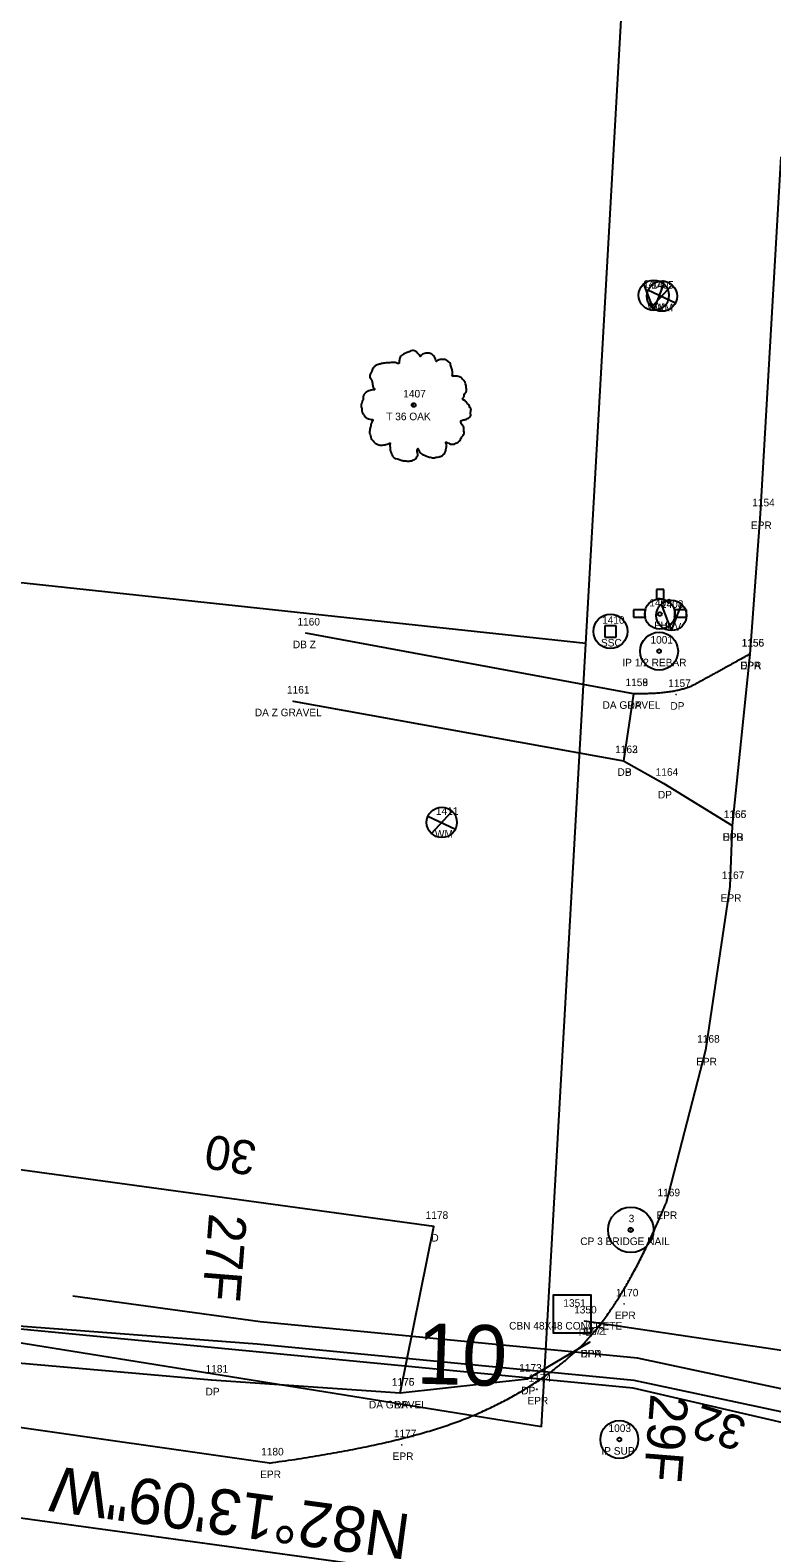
# Model space of a CAD drawing. Extents: x 1812113 to 1819860, y 1177395 to 1181185.
# Drawn here: x 1813564.5 to 1813662.4, y 1178765.4 to 1178964.5 of the extents above; entities that cross this region are included whole.
import ezdxf

# ---------------------------------------------------------------- set-up
doc = ezdxf.new("R2010")
doc.units = 0
for name, color, linetype in [('RD_EX_DR_Inlet', 7, 'Continuous'), ('RD_EX_DR_Inlet_txCode', 7, 'Continuous'), ('RD_EX_DR_Pipe', 7, 'Continuous'), ('RD_EX_DR_Pipe_txCode', 7, 'Continuous'), ('RD_EX_Driveway', 7, 'Continuous'), ('RD_EX_Driveway_txCode', 7, 'Continuous'), ('RD_EX_DV_Prop', 7, 'Continuous'), ('RD_EX_DV_Prop_txCode', 7, 'Continuous'), ('RD_EX_DV_PropPin', 7, 'Continuous'), ('RD_EX_Road', 7, 'Continuous'), ('RD_EX_Road_txCode', 7, 'Continuous'), ('RD_EX_RW', 7, 'Continuous'), ('RD_EX_UT', 7, 'Continuous'), ('RD_EX_UT_txCode', 7, 'Continuous'), ('RD_EX_VEG', 7, 'Continuous'), ('RD_EX_VEG_txCode', 7, 'Continuous'), ('RD_HC_CL', 7, 'Continuous'), ('RD_HC_Data', 7, 'Continuous'), ('RD_HC_TX_StaOther', 7, 'Continuous'), ('RD_HC_txCode', 7, 'Continuous'), ('RD_PD_ALT3_LnLine', 7, 'Continuous'), ('RD_PD_CstnLmt', 7, 'Continuous'), ('RD_PD_PatLn1', 7, 'Continuous'), ('RD_SMD_Locator', 7, 'Continuous')]:
    doc.layers.add(name, color=color, linetype=linetype)

msp = doc.modelspace()

# ---------------------------------------------------------------- linework, layer by layer
at = {"layer": 'RD_EX_DR_Inlet'}
msp.add_line((1813638.56, 1178792.49), (1813638.56, 1178797.49), dxfattribs=at)
msp.add_lwpolyline([(1813638.56, 1178792.49), (1813638.56, 1178797.49), (1813633.56, 1178797.49), (1813633.56, 1178792.49)], close=True, dxfattribs=at)
at = {"layer": 'RD_EX_DR_Pipe'}
msp.add_line((1813690.77, 1178786.15), (1813637.71, 1178794.06), dxfattribs=at)
at = {"layer": 'RD_EX_Driveway'}
for p, q in [((1813644.18, 1178876.9), (1813600.91, 1178884.9)), ((1813599.2, 1178875.92), (1813642.83, 1178868.05)), ((1813644.18, 1178876.9), (1813642.83, 1178868.05)), ((1813642.83, 1178868.05), (1813648.18, 1178865.06)), ((1813648.18, 1178865.06), (1813657.19, 1178859.48))]:
    msp.add_line(p, q, dxfattribs=at)
for points in [[(1813613.34, 1178784.52), (1813617.78, 1178806.55), (1813543.17, 1178816.74), (1813525.31, 1178791.79)], [(1813638.42, 1178791.25), (1813630.13, 1178786.38), (1813613.34, 1178784.52), (1813588.43, 1178786.24), (1813525.31, 1178791.79), (1813522.62, 1178785.74)]]:
    msp.add_lwpolyline(points, dxfattribs=at)
msp.add_open_spline([(1813659.53, 1178882.12), (1813654.68, 1178879.45), (1813649.82, 1178876.78), (1813644.18, 1178876.9)], degree=2, dxfattribs=at)
at = {"layer": 'RD_EX_DV_Prop'}
msp.add_line((1813527.37, 1178895.46), (1813637.89, 1178883.55), dxfattribs=at)
at = {"layer": 'RD_EX_DV_PropPin'}
for centre, radius in [((1813647.55, 1178882.51), 2.5), ((1813647.55, 1178882.51), 0.25), ((1813642.3, 1178778.41), 2.5), ((1813642.3, 1178778.41), 0.25)]:
    msp.add_circle(centre, radius, dxfattribs=at)
at = {"layer": 'RD_EX_Road'}
for p, q in [((1813663.63, 1178947.81), (1813660.91, 1178900.64)), ((1813660.91, 1178900.64), (1813659.53, 1178882.12)), ((1813659.53, 1178882.12), (1813657.19, 1178859.48)), ((1813657.19, 1178859.48), (1813656.91, 1178851.42)), ((1813656.91, 1178851.42), (1813653.67, 1178829.82)), ((1813653.67, 1178829.82), (1813648.43, 1178809.53)), ((1813596.09, 1178775.31), (1813522.62, 1178785.74))]:
    msp.add_line(p, q, dxfattribs=at)
msp.add_open_spline([(1813596.09, 1178775.31), (1813613.59, 1178777.71), (1813631.39, 1178785.04), (1813642.94, 1178796.31), (1813648.43, 1178809.53)], degree=2, dxfattribs=at)
at = {"layer": 'RD_EX_RW'}
for q in [(1813647.58, 1179054.5), (1813400.47, 1178817.38)]:
    msp.add_line((1813632.03, 1178780.07), q, dxfattribs=at)
at = {"layer": 'RD_EX_UT'}
for p, q in [((1813646.85, 1178927.52), (1813645.55, 1178931)), ((1813646.08, 1178930.23), (1813649.71, 1178928.51)), ((1813646.56, 1178927.93), (1813649.23, 1178930.83)), ((1813646.85, 1178927.52), (1813648.18, 1178930.96)), ((1813647.19, 1178890.64), (1813647.19, 1178889.37)), ((1813648.19, 1178890.64), (1813647.19, 1178890.64)), ((1813648.19, 1178889.34), (1813648.19, 1178890.64)), ((1813645.73, 1178887.99), (1813644.17, 1178887.99)), ((1813644.17, 1178887.99), (1813644.17, 1178886.99)), ((1813649.18, 1178885.24), (1813647.88, 1178888.72)), ((1813649.18, 1178885.24), (1813650.5, 1178888.68)), ((1813651.17, 1178887.99), (1813649.56, 1178887.99)), ((1813651.17, 1178886.99), (1813651.17, 1178887.99)), ((1813641.87, 1178885.88), (1813640.37, 1178885.88)), ((1813640.37, 1178885.88), (1813640.37, 1178884.38)), ((1813641.87, 1178884.38), (1813641.87, 1178885.88)), ((1813644.17, 1178886.99), (1813645.69, 1178886.99)), ((1813649.6, 1178886.99), (1813651.17, 1178886.99)), ((1813640.37, 1178884.38), (1813641.87, 1178884.38)), ((1813617.01, 1178860.74), (1813620.65, 1178859.02)), ((1813617.5, 1178858.44), (1813620.16, 1178861.34))]:
    msp.add_line(p, q, dxfattribs=at)
for centre, radius in [((1813646.85, 1178929.51), 2), ((1813647.92, 1178929.39), 2), ((1813647.65, 1178887.42), 2), ((1813649.18, 1178887.23), 2), ((1813641.12, 1178885.13), 2.25), ((1813647.65, 1178887.42), 0.25), ((1813618.85, 1178859.9), 2)]:
    msp.add_circle(centre, radius, dxfattribs=at)
for start, end in [(163.3387, 192.315), (74.2455, 103.2128), (347.685, 16.6613)]:
    msp.add_arc((1813647.65, 1178887.42), 2, start, end, dxfattribs=at)
at = {"layer": 'RD_EX_VEG'}
for centre, radius in [((1813615.14, 1178915.01), 0.25), ((1813615.13, 1178914.99), 0.0001)]:
    msp.add_circle(centre, radius, dxfattribs=at)
for points in [[(1813615.28, 1178922.18), (1813614.98, 1178922.21), (1813614.65, 1178922.11), (1813614.4, 1178922.01), (1813614.18, 1178921.93), (1813613.95, 1178921.83), (1813613.65, 1178921.66), (1813613.43, 1178921.46), (1813613.3, 1178921.21), (1813613.25, 1178920.98), (1813613.2, 1178920.71), (1813613.2, 1178920.53), (1813613.08, 1178920.51), (1813612.93, 1178920.53), (1813612.68, 1178920.61), (1813612.43, 1178920.61), (1813612.18, 1178920.61), (1813611.83, 1178920.58), (1813611.48, 1178920.58), (1813611.2, 1178920.53), (1813610.88, 1178920.48), (1813610.5, 1178920.36), (1813610.15, 1178920.23), (1813609.85, 1178919.98), (1813609.6, 1178919.51), (1813609.48, 1178919.16), (1813609.33, 1178918.91), (1813609.48, 1178918.46), (1813609.65, 1178918.11), (1813609.68, 1178917.91), (1813609.75, 1178917.48), (1813609.85, 1178917.26), (1813609.98, 1178917.06), (1813609.9, 1178917.03), (1813609.53, 1178916.98), (1813609.23, 1178916.88), (1813608.8, 1178916.66), (1813608.58, 1178916.43), (1813608.48, 1178916.11), (1813608.45, 1178915.76), (1813608.35, 1178915.56), (1813608.28, 1178915.28), (1813608.25, 1178915.21), (1813608.2, 1178914.88), (1813608.3, 1178914.43), (1813608.33, 1178914.08), (1813608.45, 1178913.86), (1813608.6, 1178913.68), (1813608.78, 1178913.43), (1813609.18, 1178913.21), (1813609.5, 1178913.11), (1813609.7, 1178913.09), (1813609.53, 1178912.59), (1813609.48, 1178912.24), (1813609.35, 1178911.84), (1813609.35, 1178911.76), (1813609.3, 1178911.29), (1813609.45, 1178910.96), (1813609.53, 1178910.59), (1813609.7, 1178910.36), (1813609.98, 1178910.06), (1813610.3, 1178909.84), (1813610.8, 1178909.71), (1813611.2, 1178909.74), (1813611.78, 1178909.91), (1813612.03, 1178909.99), (1813612, 1178909.81), (1813612.03, 1178909.44), (1813612.03, 1178909.01), (1813612.18, 1178908.69), (1813612.28, 1178908.41), (1813612.43, 1178908.16), (1813612.75, 1178907.94), (1813613.15, 1178907.86), (1813613.58, 1178907.71), (1813614.03, 1178907.64), (1813614.53, 1178907.61), (1813615.13, 1178907.76), (1813615.4, 1178907.89), (1813615.5, 1178908.06), (1813615.7, 1178908.44), (1813615.65, 1178908.66), (1813615.68, 1178909.26), (1813615.78, 1178909.09), (1813615.95, 1178908.74), (1813616.45, 1178908.44), (1813616.85, 1178908.26), (1813617.33, 1178908.11), (1813617.63, 1178908.04), (1813618.1, 1178908.11), (1813618.48, 1178908.19), (1813618.85, 1178908.31), (1813619.15, 1178908.59), (1813619.33, 1178908.86), (1813619.38, 1178909.14), (1813619.45, 1178909.51), (1813619.5, 1178909.69)], [(1813619.5, 1178909.69), (1813619.43, 1178909.86), (1813619.38, 1178910.11), (1813619.45, 1178910.09), (1813619.62, 1178910.04), (1813619.9, 1178909.91), (1813620.12, 1178909.84), (1813620.45, 1178909.86), (1813620.72, 1178909.96), (1813621.17, 1178910.24), (1813621.45, 1178910.71), (1813621.72, 1178911.11), (1813621.8, 1178911.44), (1813621.75, 1178911.66), (1813621.72, 1178912.16), (1813621.52, 1178912.41), (1813621.47, 1178912.54), (1813621.37, 1178912.94), (1813621.45, 1178912.99), (1813621.72, 1178913.04), (1813622.1, 1178913.16), (1813622.37, 1178913.28), (1813622.6, 1178913.46), (1813622.67, 1178913.68), (1813622.65, 1178914.08), (1813622.7, 1178914.48), (1813622.62, 1178914.63), (1813622.52, 1178914.78), (1813622.45, 1178914.98), (1813622.3, 1178915.13), (1813622.2, 1178915.28), (1813622.1, 1178915.38), (1813621.97, 1178915.53), (1813621.8, 1178915.66), (1813621.65, 1178915.71), (1813621.6, 1178915.86), (1813621.75, 1178916.06), (1813621.8, 1178916.16), (1813621.82, 1178916.38), (1813622.05, 1178916.73), (1813622.1, 1178917.13), (1813622.05, 1178917.56), (1813622, 1178917.83), (1813621.85, 1178918.11), (1813621.65, 1178918.36), (1813621.52, 1178918.53), (1813621.35, 1178918.66), (1813621.02, 1178918.78), (1813620.77, 1178918.83), (1813620.42, 1178918.83), (1813620.22, 1178918.88), (1813620.25, 1178918.93), (1813620.25, 1178919.08), (1813620.25, 1178919.36), (1813620.17, 1178919.81), (1813620.02, 1178920.31), (1813620.02, 1178920.33), (1813619.92, 1178920.58), (1813619.7, 1178920.78), (1813619.52, 1178920.88), (1813619.33, 1178921.01), (1813619.08, 1178921.03), (1813618.78, 1178921.03), (1813618.5, 1178920.98), (1813618.3, 1178920.88), (1813618.13, 1178920.76), (1813618.05, 1178920.91), (1813617.95, 1178921.21), (1813617.9, 1178921.36), (1813617.75, 1178921.53), (1813617.53, 1178921.73), (1813617.08, 1178921.86), (1813616.45, 1178921.78), (1813616.15, 1178921.58), (1813616, 1178921.41), (1813615.95, 1178921.53), (1813615.75, 1178921.73), (1813615.65, 1178921.91), (1813615.48, 1178922.03), (1813615.33, 1178922.13), (1813615.23, 1178922.18)]]:
    msp.add_spline(points, degree=3, dxfattribs=at)
at = {"layer": 'RD_HC_CL'}
msp.add_line((1813641.28, 1178757.34), (1813538.22, 1178771.42), dxfattribs=at)
at = {"layer": 'RD_HC_Data'}
for radius in [3, 0.282]:
    msp.add_circle((1813643.81, 1178806.09), radius, dxfattribs=at)
at = {"layer": 'RD_PD_ALT3_LnLine'}
for p, q in [((1813594.87, 1178793.96), (1813570.1, 1178797.34)), ((1813594.46, 1178790.99), (1813544.52, 1178794.78)), ((1813644.68, 1178789.17), (1813594.87, 1178793.96)), ((1813644.27, 1178786.2), (1813594.46, 1178790.99)), ((1813700.68, 1178777.2), (1813644.68, 1178789.17)), ((1813699.62, 1178774.39), (1813644.27, 1178786.2))]:
    msp.add_line(p, q, dxfattribs=at)
at = {"layer": 'RD_PD_CstnLmt'}
for p, q in [((1813594.33, 1178789.99), (1813544.52, 1178794.78)), ((1813644.14, 1178785.21), (1813594.33, 1178789.99)), ((1813698.92, 1178772.52), (1813644.14, 1178785.21))]:
    msp.add_line(p, q, dxfattribs=at)
at = {"layer": 'RD_PD_PatLn1'}
msp.add_line((1813616.11, 1178760.78), (1813027.99, 1178841.14), dxfattribs=at)
at = {"layer": 'RD_SMD_Locator'}
for centre in [(1813660.91, 1178900.64), (1813600.91, 1178884.9), (1813659.53, 1178882.12), (1813659.53, 1178882.12), (1813599.2, 1178875.92), (1813644.18, 1178876.9), (1813644.18, 1178876.9), (1813649.82, 1178876.78), (1813642.83, 1178868.05), (1813642.83, 1178868.05), (1813648.18, 1178865.06), (1813657.19, 1178859.48), (1813657.19, 1178859.48), (1813656.91, 1178851.42), (1813653.67, 1178829.82), (1813648.43, 1178809.53), (1813617.78, 1178806.55), (1813643.81, 1178806.09), (1813642.94, 1178796.31), (1813637.71, 1178794.06), (1813638.42, 1178791.25), (1813638.42, 1178791.25), (1813588.43, 1178786.24), (1813630.13, 1178786.38), (1813613.34, 1178784.52), (1813613.34, 1178784.52), (1813631.39, 1178785.04), (1813613.59, 1178777.71), (1813596.09, 1178775.31)]:
    msp.add_circle(centre, 0.001, dxfattribs=at)

# ---------------------------------------------------------------- texts
at = {"layer": 'RD_EX_DR_Inlet_txCode'}
for s, p in [('1351', (1813634.9, 1178795.94)), ('CBN 48X48 CONCRETE', (1813627.74, 1178792.94))]:
    msp.add_text(s, height=1, dxfattribs=at).set_placement(p)
at = {"layer": 'RD_EX_DR_Pipe_txCode'}
for s, p in [('1350', (1813636.33, 1178795.06)), ('PB', (1813636.93, 1178792.06))]:
    msp.add_text(s, height=1, dxfattribs=at).set_placement(p)
at = {"layer": 'RD_EX_Driveway_txCode'}
for s, p in [('1160', (1813599.78, 1178885.9)), ('DB Z', (1813599.18, 1178882.9)), ('1156', (1813658.44, 1178883.12)), ('DPA', (1813658.26, 1178880.12)), ('1161', (1813598.4, 1178876.92)), ('1158', (1813643.11, 1178877.9)), ('1159', (1813643.11, 1178877.9)), ('1157', (1813648.76, 1178877.78)), ('DA GRAVEL', (1813640.08, 1178874.9)), ('DP', (1813643.4, 1178874.9)), ('DA Z GRAVEL', (1813594.15, 1178873.92)), ('DP', (1813649.04, 1178874.78)), ('1162', (1813641.75, 1178869.05)), ('1163', (1813641.75, 1178869.05)), ('DB', (1813642.05, 1178866.05)), ('DP', (1813642.05, 1178866.05)), ('1164', (1813647.1, 1178866.06)), ('DP', (1813647.4, 1178863.06)), ('1165', (1813656.1, 1178860.48)), ('DPB', (1813655.94, 1178857.48)), ('1178', (1813616.72, 1178807.55)), ('D', (1813617.47, 1178804.55)), ('1172', (1813637.36, 1178792.25)), ('DPA', (1813637.16, 1178789.25)), ('1181', (1813587.65, 1178787.24)), ('1173', (1813629.07, 1178787.38)), ('1176', (1813612.25, 1178785.52)), ('1175', (1813612.27, 1178785.52)), ('DP', (1813587.65, 1178784.24)), ('DP', (1813629.35, 1178784.38)), ('DA GRAVEL', (1813609.23, 1178782.52)), ('DP', (1813612.56, 1178782.52))]:
    msp.add_text(s, height=1, dxfattribs=at).set_placement(p)
at = {"layer": 'RD_EX_DV_Prop_txCode'}
for s, p in [('1001', (1813646.41, 1178883.51)), ('IP 1/2 REBAR', (1813642.7, 1178880.51)), ('1003', (1813640.87, 1178779.41)), ('IP SUP', (1813639.93, 1178776.41))]:
    msp.add_text(s, height=1, dxfattribs=at).set_placement(p)
at = {"layer": 'RD_EX_Road_txCode'}
for s, p in [('1154', (1813659.85, 1178901.64)), ('EPR', (1813659.68, 1178898.64)), ('1155', (1813658.47, 1178883.12)), ('EPR', (1813658.3, 1178880.12)), ('1166', (1813656.08, 1178860.48)), ('EPR', (1813655.96, 1178857.48)), ('1167', (1813655.83, 1178852.42)), ('EPR', (1813655.68, 1178849.42)), ('1168', (1813652.58, 1178830.82)), ('EPR', (1813652.44, 1178827.82)), ('1169', (1813647.34, 1178810.53)), ('EPR', (1813647.2, 1178807.53)), ('1170', (1813641.84, 1178797.31)), ('EPR', (1813641.71, 1178794.31)), ('1171', (1813637.65, 1178792.25)), ('EPR', (1813637.2, 1178789.25)), ('1174', (1813630.32, 1178786.04)), ('EPR', (1813630.16, 1178783.04)), ('1177', (1813612.52, 1178778.71)), ('1180', (1813594.99, 1178776.31)), ('EPR', (1813612.36, 1178775.71)), ('EPR', (1813594.86, 1178773.31))]:
    msp.add_text(s, height=1, dxfattribs=at).set_placement(p)
at = {"layer": 'RD_EX_UT_txCode'}
for s, p in [('1406', (1813645.44, 1178930.51)), ('1405', (1813646.53, 1178930.39)), ('WV', (1813646, 1178927.51)), ('WM', (1813647.01, 1178927.39)), ('1409', (1813646.26, 1178888.42)), ('1408', (1813647.79, 1178888.23)), ('1410', (1813640.02, 1178886.13)), ('FH', (1813646.91, 1178885.42)), ('WV', (1813648.32, 1178885.23)), ('SSC', (1813639.87, 1178883.13)), ('1411', (1813618.07, 1178860.9)), ('WM', (1813617.94, 1178857.9))]:
    msp.add_text(s, height=1, dxfattribs=at).set_placement(p)
at = {"layer": 'RD_EX_VEG_txCode'}
for s, p in [('1407', (1813613.76, 1178916.01)), ('T 36 OAK', (1813611.51, 1178913.01))]:
    msp.add_text(s, height=1, dxfattribs=at).set_placement(p)
at = {"layer": 'RD_HC_Data'}
msp.add_text('N82%%d13\'09"W', height=6, rotation=172.2191, dxfattribs=at).set_placement((1813614.93, 1178768.47))
at = {"layer": 'RD_HC_TX_StaOther'}
msp.add_text('10', height=8, rotation=358.2694, dxfattribs=at).set_placement((1813615.46, 1178785.8))
at = {"layer": 'RD_HC_txCode'}
for s, p in [('3', (1813643.53, 1178807.09)), ('CP 3 BRIDGE NAIL', (1813637.14, 1178804.09))]:
    msp.add_text(s, height=1, dxfattribs=at).set_placement(p)
at = {"layer": 'RD_PD_ALT3_LnLine'}
for s, height, rotation, p in [('30', 4.5, 170.8507, (1813594.61, 1178817.66)), ('27F', 5, 265.3892, (1813588.13, 1178808.38)), ('29F', 5, 265.3892, (1813646.44, 1178784.53)), ('32', 4.5, 162.685, (1813659.37, 1178781.12))]:
    msp.add_text(s, height=height, rotation=rotation, dxfattribs=at).set_placement(p)

doc.saveas('drawing.dxf')
